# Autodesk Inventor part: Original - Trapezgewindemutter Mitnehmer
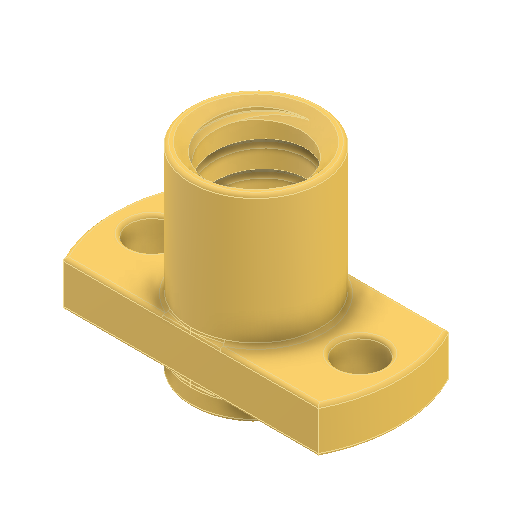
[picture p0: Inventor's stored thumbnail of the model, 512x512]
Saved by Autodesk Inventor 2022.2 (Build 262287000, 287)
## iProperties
Created: 2024-09
Part Number: Original - Trapezgewindemutter Mitnehmer
Material: Generico
Document SubType Name: Modeling
Designer: 18907419
Density: 1 g/cm^3
Appearance: Default
Author: 18907419
Revision Number: ANY
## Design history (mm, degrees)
feature "Schnitt-Austragung1"
node "Solido1"
